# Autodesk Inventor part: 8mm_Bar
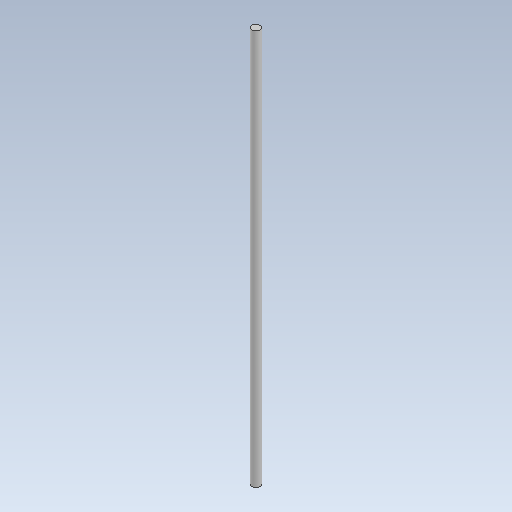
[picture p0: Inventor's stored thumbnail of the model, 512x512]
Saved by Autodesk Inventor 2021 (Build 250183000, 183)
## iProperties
Created: 2026-10
Part Number: 8mm_Bar
Material: Steel
Document SubType Name: Modeling
Designer: hp
Density: 7.85 g/cm^3
Appearance: Default
Author: hp
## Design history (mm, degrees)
feature "Body1"
body "Solid1"
